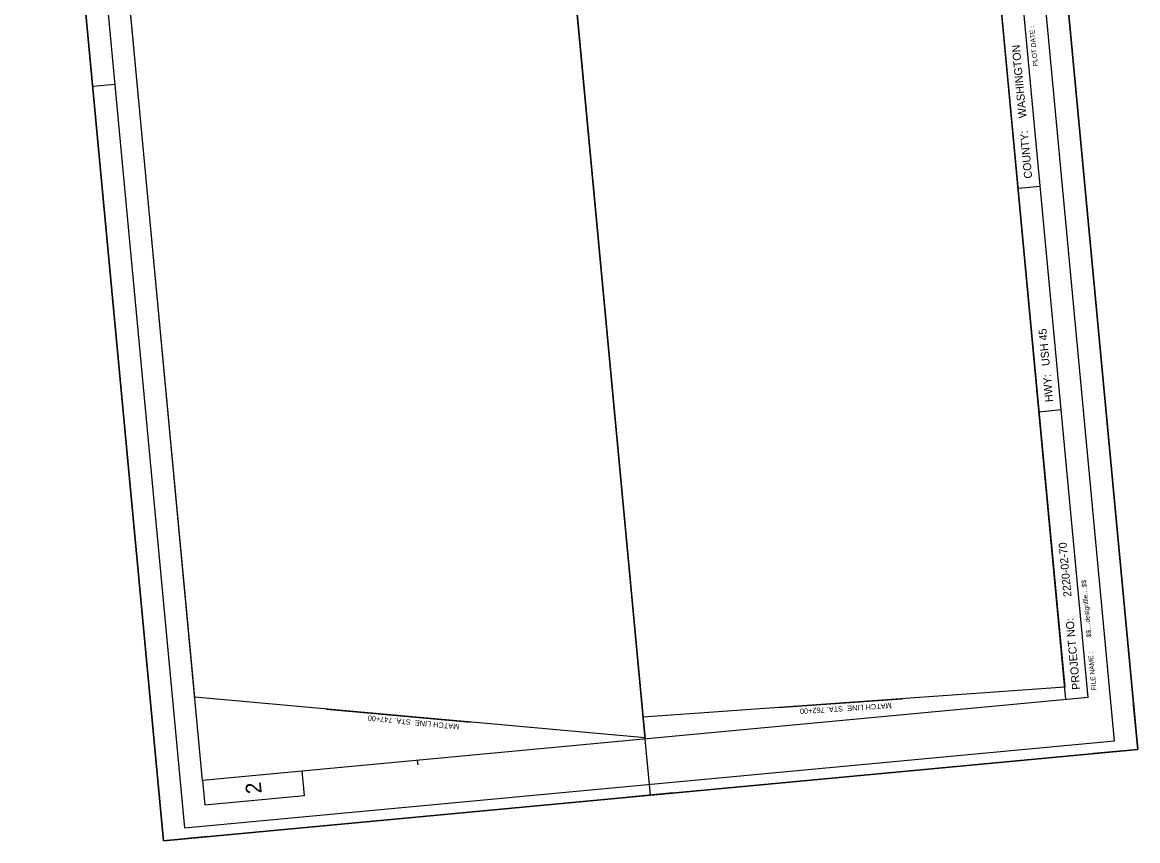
# Model space of a CAD drawing. Extents: x 356181 to 357435, y 196482 to 198277.
# Drawn here: x 356181 to 357435, y 196482 to 197402 of the extents above; entities that cross this region are included whole.
import ezdxf

# ---------------------------------------------------------------- set-up
doc = ezdxf.new("R2010")
doc.units = 0
for name, color, linetype in [('Default', 7, 'Continuous'), ('P_SHTIDX_4 [KAPUR_CADDS_LEVELS]', 7, 'Continuous'), ('P_TXT_Plan 1 [KAPUR_CADDS_LEVELS]', 7, 'Continuous'), ('P_TXT_Plan 3 [KAPUR_CADDS_LEVELS]', 7, 'Continuous'), ('P_TXT_Plan 4 [KAPUR_CADDS_LEVELS]', 7, 'Continuous'), ('P_TXT_Plan 4_TEXT [KAPUR_CADDS_LEVELS]', 7, 'Continuous'), ('PLT_Sheet_Info', 7, 'Continuous')]:
    doc.layers.add(name, color=color, linetype=linetype)

msp = doc.modelspace()

# ---------------------------------------------------------------- linework, layer by layer
at = {"layer": 'Default'}
for points in [[(356241.5, 198068.7), (356702.1, 198161.1), (356734.8, 198164.1), (356881.8, 196596), (356881.7, 196597.3), (356375.2, 196643.3)], [(356241.5, 198068.7), (356702.1, 198161.1), (356734.8, 198164.1), (356881.8, 196596), (356881.7, 196597.3), (356375.2, 196643.3)], [(356241.5, 198068.7), (356702.1, 198161.1), (356734.8, 198164.1), (356881.8, 196596), (356881.7, 196597.3), (356375.2, 196643.3)], [(356241.5, 198068.7), (356702.1, 198161.1), (356734.8, 198164.1), (356881.8, 196596), (356881.7, 196597.3), (356375.2, 196643.3)], [(356241.5, 198068.7), (356702.1, 198161.1), (356734.8, 198164.1), (356881.8, 196596), (356881.7, 196597.3), (356375.2, 196643.3)], [(356241.5, 198068.7), (356702.1, 198161.1), (356734.8, 198164.1), (356881.8, 196596), (356881.7, 196597.3), (356375.2, 196643.3)], [(356739.4, 198114.4), (357063.7, 198137.5), (357213.3, 198148.1), (357353.4, 196654.3), (357353.4, 196654.3), (356879.5, 196620.6)], [(356739.4, 198114.4), (357063.7, 198137.5), (357213.3, 198148.1), (357353.4, 196654.3), (357353.4, 196654.3), (356879.5, 196620.6)], [(356739.4, 198114.4), (357063.7, 198137.5), (357213.3, 198148.1), (357353.4, 196654.3), (357353.4, 196654.3), (356879.5, 196620.6)], [(356739.4, 198114.4), (357063.7, 198137.5), (357213.3, 198148.1), (357353.4, 196654.3), (357353.4, 196654.3), (356879.5, 196620.6)], [(356739.4, 198114.4), (357063.7, 198137.5), (357213.3, 198148.1), (357353.4, 196654.3), (357353.4, 196654.3), (356879.5, 196620.6)], [(356739.4, 198114.4), (357063.7, 198137.5), (357213.3, 198148.1), (357353.4, 196654.3), (357353.4, 196654.3), (356879.5, 196620.6)]]:
    msp.add_lwpolyline(points, close=True, dxfattribs=at)
at = {"layer": 'P_SHTIDX_4 [KAPUR_CADDS_LEVELS]'}
for p, q in [((357379.6, 196642.7), (357232.6, 198210.8)), ((357354.7, 196640.4), (357207.7, 198208.5)), ((356384, 196549.3), (356236.9, 198117.4)), ((356881.8, 196596), (356763.6, 197856.3)), ((356262.9, 197305.6), (356258.2, 197355.3)), ((356260.5, 197330.5), (356285.4, 197332.8)), ((357325.7, 197217.7), (357300.8, 197215.3)), ((357349.3, 196966.3), (357324.4, 196963.9)), ((357379.6, 196642.7), (356384, 196549.3)), ((356878.3, 196633.4), (356878.3, 196633.4)), ((357435.3, 196584.4), (357430.7, 196634.2)), ((356887.7, 196533), (356881.8, 196596)), ((357435.3, 196584.4), (357385.5, 196579.7)), ((356625.4, 196572), (356625.9, 196567)), ((356340.1, 196481.7), (356335.5, 196531.5)), ((356912.6, 196535.4), (356862.8, 196530.7)), ((356389.9, 196486.4), (356340.1, 196481.7))]:
    msp.add_line(p, q, dxfattribs=at)
msp.add_lwpolyline([(356384, 196549.3), (356386.6, 196521.9), (356498.6, 196532.5), (356496, 196559.8)], close=True, dxfattribs=at)
at = {"layer": 'P_TXT_Plan 1 [KAPUR_CADDS_LEVELS]'}
msp.add_line((356881.8, 196596), (356734.8, 198164.1), dxfattribs=at)
at = {"layer": 'P_TXT_Plan 4 [KAPUR_CADDS_LEVELS]'}
for p, q in [((356523.5, 196629.8), (356685.4, 196615.1)), ((357031.5, 196631.4), (357170.4, 196641.3))]:
    msp.add_line(p, q, dxfattribs=at)
at = {"layer": 'P_TXT_Plan 4_TEXT [KAPUR_CADDS_LEVELS]'}
msp.add_lwpolyline([(356340.1, 196481.7), (356181.4, 198174.3), (357276.6, 198277), (357435.3, 196584.4)], close=True, dxfattribs=at)
at = {"layer": 'PLT_Sheet_Info'}
for points in [[(357435.3, 196584.4), (357276.6, 198277), (356181.4, 198174.3), (356340.1, 196481.7)], [(357409.3, 196594), (357254.8, 198241.8), (356209.4, 198143.7), (356363.9, 196496)]]:
    msp.add_lwpolyline(points, close=True, dxfattribs=at)

# ---------------------------------------------------------------- texts
at = {"layer": 'P_SHTIDX_4 [KAPUR_CADDS_LEVELS]'}
for s, height, rotation, p in [('PLOT DATE :', 5.4, 95.3578, (357323.1, 197353)), (' WASHINGTON', 9, 95.3579, (357310.7, 197291.6)), ('COUNTY:', 9, 95.3579, (357316.8, 197226.9)), (' USH 45', 9, 95.3579, (357336.9, 197012.8)), ('HWY:', 9, 95.3579, (357340.4, 196975.5)), (' 2220-02-70', 9, 95.3579, (357361.3, 196753)), ('$$....designfile....$$', 5.4, 95.3578, (357383.3, 196710.8)), ('PROJECT NO:', 9, 95.3579, (357370.7, 196651.9)), ('FILE NAME :', 5.4, 95.3579, (357388.9, 196651.1)), ('2', 17.5, 95.3579, (356450.6, 196535.2))]:
    msp.add_text(s, height=height, rotation=rotation, dxfattribs=at).set_placement(p)
at = {"layer": 'P_TXT_Plan 3 [KAPUR_CADDS_LEVELS]'}
for s, rotation, p in [('MATCH LINE  STA. 762+00', 183.6562, (357158.6, 196636.7)), ('MATCH LINE  STA. 747+00', 174.3993, (356672.9, 196612.6))]:
    msp.add_text(s, height=6, rotation=rotation, dxfattribs=at).set_placement(p)

doc.saveas('drawing.dxf')
